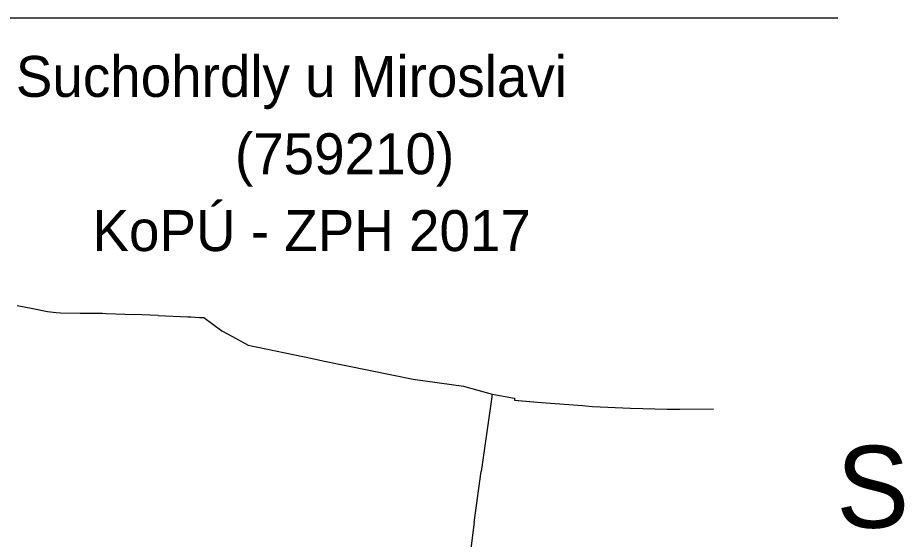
# Model space of a CAD drawing. Extents: x -623137 to -616791, y -1192758 to -1186540.
# Drawn here: x -618632 to -616901, y -1187981 to -1186962 of the extents above; entities that cross this region are included whole.
import ezdxf

# ---------------------------------------------------------------- set-up
doc = ezdxf.new("R2010")
doc.units = 0
for name, color, linetype in [('Legenda', 7, 'Continuous'), ('Vrstva 13', 7, 'Continuous'), ('Vzdy červené', 7, 'Continuous')]:
    doc.layers.add(name, color=color, linetype=linetype)

msp = doc.modelspace()

# ---------------------------------------------------------------- linework, layer by layer
at = {"layer": 'Vrstva 13'}
for p, q in [((-618633.5, -1187524.5), (-618602.8, -1187530.5)), ((-618602.8, -1187530.5), (-618574.1, -1187536)), ((-618574.1, -1187536), (-618557.5, -1187537.9)), ((-618557.5, -1187537.9), (-618548.5, -1187538.9)), ((-618548.5, -1187538.9), (-618510.1, -1187539.3)), ((-618510.1, -1187539.3), (-618500.9, -1187539.4)), ((-618500.9, -1187539.4), (-618466.5, -1187539.8)), ((-618466.5, -1187539.8), (-618459.8, -1187540.1)), ((-618459.8, -1187540.1), (-618405.1, -1187542.3)), ((-618358.2, -1187544.3), (-618405.1, -1187542.3)), ((-618358.2, -1187544.3), (-618299.8, -1187546.7)), ((-618299.8, -1187546.7), (-618293.9, -1187547)), ((-618293.9, -1187547), (-618277.3, -1187547.7)), ((-618277.3, -1187547.7), (-618268.6, -1187548)), ((-618268.6, -1187548), (-618233.4, -1187573.9)), ((-618233.4, -1187573.9), (-618212.8, -1187585.3)), ((-618212.8, -1187585.3), (-618182.4, -1187602.2)), ((-618182.4, -1187602.2), (-618056.9, -1187627.8)), ((-618056.9, -1187627.8), (-618036.5, -1187632.4)), ((-618036.5, -1187632.4), (-617898.6, -1187660.4)), ((-617898.6, -1187660.4), (-617859.7, -1187668.4)), ((-617859.7, -1187668.4), (-617859.7, -1187668.4)), ((-617859.7, -1187668.4), (-617762, -1187682.3)), ((-617762, -1187682.3), (-617706, -1187697.6)), ((-617706, -1187697.6), (-617706.6, -1187702.6)), ((-617706, -1187697.6), (-617661.8, -1187705.7)), ((-617706, -1187697.6), (-617661.8, -1187705.7)), ((-617706.6, -1187703.3), (-617709.2, -1187721.3)), ((-617706.6, -1187702.6), (-617706.6, -1187703.3)), ((-617661.8, -1187705.7), (-617661.9, -1187709.7)), ((-617661.8, -1187705.7), (-617661.9, -1187709.7)), ((-617661.9, -1187709.7), (-617625.6, -1187712.9)), ((-617661.9, -1187709.7), (-617609.6, -1187714.3)), ((-617609.6, -1187714.3), (-617529.5, -1187719.9)), ((-617709.2, -1187721.3), (-617727, -1187848.7)), ((-617529.5, -1187719.9), (-617509.7, -1187721.7)), ((-617509.7, -1187721.7), (-617499.7, -1187722.5)), ((-617509.7, -1187721.7), (-617435.6, -1187725.3)), ((-617435.6, -1187725.3), (-617364.2, -1187727.1)), ((-617364.2, -1187727.1), (-617339.4, -1187727)), ((-617339.4, -1187727), (-617273.4, -1187726.2)), ((-617740.6, -1187948.5), (-617727, -1187848.7)), ((-617741.2, -1187953.4), (-617749.6, -1188015.2)), ((-617740.6, -1187948.5), (-617741.2, -1187953.4))]:
    msp.add_line(p, q, dxfattribs=at)
at = {"layer": 'Vzdy červené'}
msp.add_line((-623098.3, -1186962.2), (-617030.7, -1186962.2), dxfattribs=at)

# ---------------------------------------------------------------- texts
at = {"layer": 'Legenda'}
for s, height, p in [('Suchohrdly u Miroslavi', 80, (-618635.9, -1187116.9)), ('(759210)', 80, (-618208, -1187268)), ('KoPÚ - ZPH 2017', 80, (-618486.3, -1187418.2)), ('S', 160, (-617033.8, -1187958.8))]:
    msp.add_text(s, height=height, dxfattribs=at).set_placement(p)

doc.saveas('drawing.dxf')
